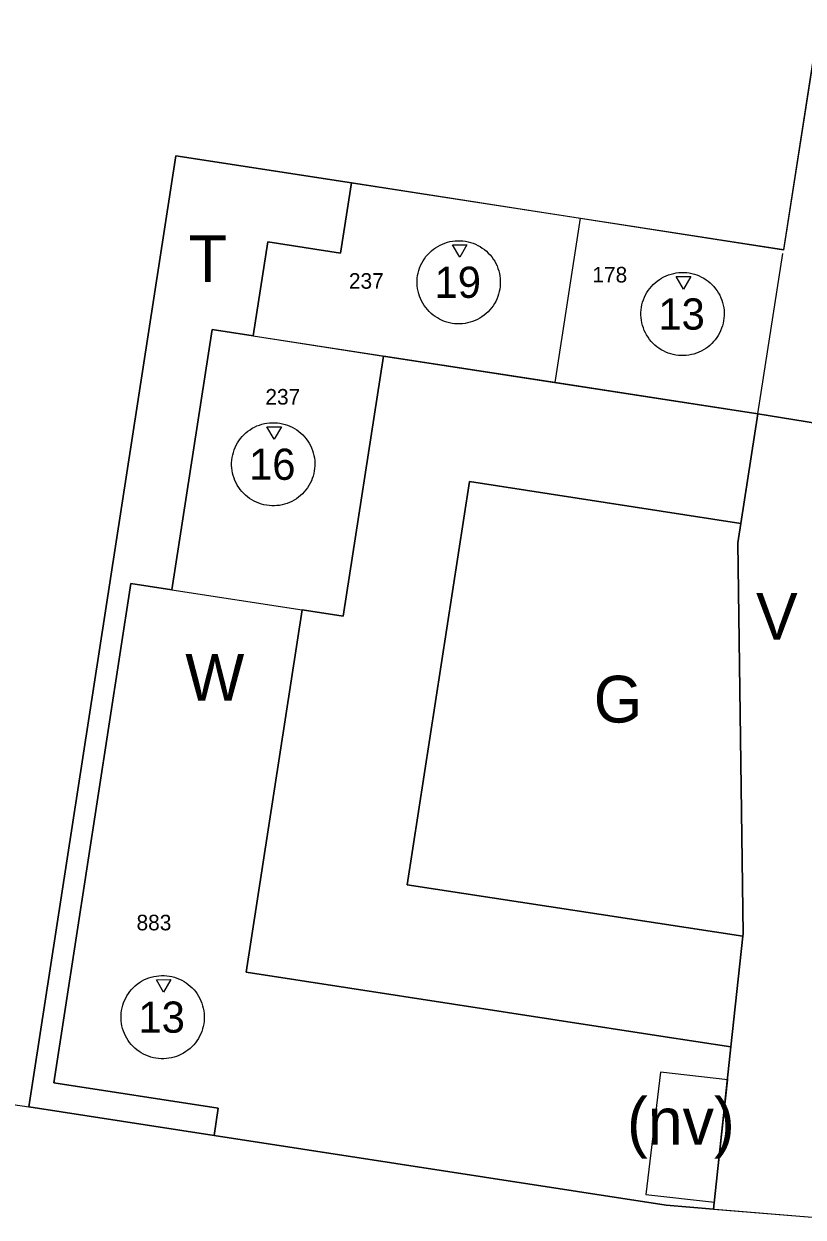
# Model space of a CAD drawing. Extents: x 104705 to 105186, y 424858 to 425816.
# Drawn here: x 104992.1 to 105048.3, y 424958.5 to 425044.5 of the extents above; entities that cross this region are included whole.
import ezdxf

# ---------------------------------------------------------------- set-up
doc = ezdxf.new("R2010")
doc.units = 0
for name, color, linetype in [('BP_ALG_bestemminggrens', 7, 'Continuous'), ('BP_BPG_Plangebied', 7, 'Continuous'), ('BP_BV_Bouwvlak', 7, 'Continuous'), ('BP_DB_Waarde - Archeologie - 3', 7, 'Continuous'), ('BP_EB_Groen', 7, 'Continuous'), ('BP_EB_Tuin', 7, 'Continuous'), ('BP_EB_Verkeer', 7, 'Continuous'), ('BP_EB_Wonen', 7, 'Continuous'), ('BP_FA_gemengd', 7, 'Continuous'), ('BP_FA_nutsvoorziening', 7, 'Continuous'), ('BP_MV_maatvoering', 7, 'Continuous'), ('BP_TXT_tekst', 7, 'Continuous'), ('Default', 7, 'Continuous')]:
    doc.layers.add(name, color=color, linetype=linetype)

msp = doc.modelspace()

# ---------------------------------------------------------------- linework, layer by layer
at = {"layer": 'BP_ALG_bestemminggrens'}
for p, q in [((105046.867, 425028.264), (105049.408, 425044.533)), ((105014.92, 425028), (105015.703, 425033.072)), ((105015.703, 425033.072), (105046.867, 425028.264)), ((105008.627, 425022.021), (105009.674, 425028.81)), ((105009.674, 425028.81), (105014.92, 425028)), ((105002.768, 425003.717), (105005.662, 425022.479)), ((105005.662, 425022.479), (105008.627, 425022.021)), ((105043.561, 425007.108), (105045.014, 425016.407)), ((105045.014, 425016.408), (105076.846, 425011.136)), ((105045.014, 425016.407), (105076.846, 425011.136)), ((105019.721, 424982.44), (105024.208, 425011.523)), ((105024.208, 425011.523), (105043.779, 425008.503)), ((105043.942, 424978.904), (105043.561, 425007.108)), ((104994.246, 424968.157), (104999.803, 425004.175)), ((104999.803, 425004.175), (105002.768, 425003.717)), ((105043.922, 424978.723), (105019.721, 424982.44)), ((105041.81, 424959.043), (105043.942, 424978.904)), ((105006.105, 424966.327), (104994.246, 424968.157)), ((105005.8, 424964.351), (105006.105, 424966.327)), ((105038.397, 424959.322), (105005.8, 424964.351)), ((105038.397, 424959.322), (105041.81, 424959.043))]:
    msp.add_line(p, q, dxfattribs=at)
msp.add_lwpolyline([(105005.8, 424964.351), (104992.458, 424966.409), (105003.045, 425035.025), (105015.703, 425033.072)], dxfattribs=at)
at = {"layer": 'BP_BPG_Plangebied'}
msp.add_line((104977.634, 424968.696), (104992.458, 424966.409), dxfattribs=at)
msp.add_lwpolyline([(104992.458, 424966.409), (105038.397, 424959.322), (105048.93, 424958.462), (105050.429, 424958.51)], dxfattribs=at)
at = {"layer": 'BP_BV_Bouwvlak'}
for p, q in [((105046.867, 425028.264), (105049.409, 425044.533)), ((105014.92, 425028), (105015.703, 425033.072)), ((105015.703, 425033.072), (105046.867, 425028.264)), ((105008.627, 425022.021), (105009.674, 425028.81)), ((105009.674, 425028.81), (105014.92, 425028)), ((105002.768, 425003.717), (105005.662, 425022.479)), ((105005.662, 425022.479), (105008.627, 425022.021)), ((105018.016, 425020.573), (105015.121, 425001.811)), ((105045.014, 425016.408), (105018.016, 425020.573)), ((105045.014, 425016.407), (105045.014, 425016.408)), ((105076.846, 425011.136), (105045.014, 425016.407)), ((104994.246, 424968.157), (104999.803, 425004.175)), ((104999.803, 425004.175), (105002.768, 425003.717)), ((105012.156, 425002.269), (105008.124, 424976.134)), ((105015.121, 425001.811), (105012.156, 425002.269)), ((105008.124, 424976.134), (105043.061, 424970.744)), ((105006.105, 424966.327), (104994.246, 424968.157)), ((105005.8, 424964.351), (105006.105, 424966.327)), ((105038.397, 424959.322), (105005.8, 424964.351))]:
    msp.add_line(p, q, dxfattribs=at)
msp.add_lwpolyline([(105043.061, 424970.744), (105041.81, 424959.043), (105038.397, 424959.322)], dxfattribs=at)
at = {"layer": 'BP_DB_Waarde - Archeologie - 3'}
msp.add_line((104977.634, 424968.696), (104992.458, 424966.409), dxfattribs=at)
msp.add_lwpolyline([(104992.458, 424966.409), (105038.397, 424959.322), (105048.93, 424958.462), (105050.429, 424958.51), (105049.681, 424981.898), (105049.681, 424981.898)], dxfattribs=at)
at = {"layer": 'BP_EB_Groen'}
for p, q in [((105024.208, 425011.523), (105019.721, 424982.44)), ((105043.779, 425008.503), (105024.208, 425011.523)), ((105043.561, 425007.108), (105043.779, 425008.503)), ((105043.942, 424978.904), (105043.561, 425007.108)), ((105019.721, 424982.44), (105043.922, 424978.723)), ((105043.922, 424978.723), (105043.942, 424978.904))]:
    msp.add_line(p, q, dxfattribs=at)
at = {"layer": 'BP_EB_Tuin'}
for p, q in [((104994.246, 424968.157), (104999.803, 425004.175)), ((104999.803, 425004.175), (105002.768, 425003.717))]:
    msp.add_line(p, q, dxfattribs=at)
for points in [[(105015.703, 425033.072), (105003.045, 425035.025), (104992.458, 424966.409), (105005.8, 424964.351)], [(105009.674, 425028.81), (105014.92, 425028), (105015.703, 425033.072)], [(105002.768, 425003.717), (105005.662, 425022.479), (105008.627, 425022.021), (105009.674, 425028.81)], [(105005.8, 424964.351), (105006.105, 424966.327), (104994.246, 424968.157)]]:
    msp.add_lwpolyline(points, dxfattribs=at)
at = {"layer": 'BP_EB_Verkeer'}
for p, q in [((105046.866, 425028.264), (105048.674, 425039.829)), ((104992.458, 424966.409), (105003.045, 425035.025)), ((105003.045, 425035.025), (105015.703, 425033.072)), ((105015.703, 425033.072), (105032.211, 425030.525)), ((105032.211, 425030.525), (105046.866, 425028.264)), ((105045.014, 425016.408), (105043.779, 425008.503)), ((105064.746, 425013.14), (105045.014, 425016.408)), ((105043.779, 425008.503), (105043.561, 425007.108)), ((105043.561, 425007.108), (105043.942, 424978.904)), ((105043.942, 424978.904), (105043.922, 424978.723)), ((104977.634, 424968.696), (104992.458, 424966.409))]:
    msp.add_line(p, q, dxfattribs=at)
for points in [[(105043.922, 424978.723), (105043.066, 424970.744), (105041.81, 424959.043)], [(105041.81, 424959.043), (105048.93, 424958.462), (105050.429, 424958.51)]]:
    msp.add_lwpolyline(points, dxfattribs=at)
at = {"layer": 'BP_EB_Wonen'}
for p, q in [((105030.381, 425018.665), (105018.016, 425020.573)), ((105045.014, 425016.408), (105030.381, 425018.665)), ((105043.779, 425008.503), (105045.014, 425016.408)), ((105008.124, 424976.134), (105038.007, 424971.524))]:
    msp.add_line(p, q, dxfattribs=at)
for points in [[(105077.145, 425011.387), (105081.418, 425038.738), (105049.408, 425044.533), (105049.287, 425043.758), (105046.856, 425028.204), (105015.703, 425033.072), (105014.92, 425028), (105009.674, 425028.81), (105008.627, 425022.021), (105005.662, 425022.479), (105002.768, 425003.717), (104999.803, 425004.175), (104994.246, 424968.157), (105006.105, 424966.327), (105005.8, 424964.351), (105038.397, 424959.322)], [(105018.016, 425020.573), (105015.121, 425001.811), (105012.156, 425002.269), (105008.124, 424976.134)], [(105038.397, 424959.322), (105041.81, 424959.043), (105043.061, 424970.744), (105038.007, 424971.524), (105008.124, 424976.134), (105012.156, 425002.269), (105015.121, 425001.811), (105018.016, 425020.573), (105045.014, 425016.407), (105077.145, 425011.387)], [(105038.007, 424971.524), (105043.061, 424970.744), (105043.922, 424978.723), (105019.721, 424982.44), (105024.208, 425011.523), (105043.779, 425008.503)]]:
    msp.add_lwpolyline(points, dxfattribs=at)
at = {"layer": 'BP_FA_gemengd'}
msp.add_lwpolyline([(105045.014, 425016.408), (105077.145, 425011.387), (105081.418, 425038.738), (105049.408, 425044.533), (105049.287, 425043.758), (105046.856, 425028.204), (105015.703, 425033.072), (105014.92, 425028), (105009.674, 425028.81), (105008.627, 425022.021), (105045.066, 425016.4)], dxfattribs=at)
at = {"layer": 'BP_FA_nutsvoorziening'}
msp.add_lwpolyline([(105036.94, 424960.104), (105041.881, 424959.534), (105042.842, 424968.375), (105037.978, 424968.913)], close=True, dxfattribs=at)
at = {"layer": 'BP_MV_maatvoering'}
for p, q in [((105030.381, 425018.665), (105032.211, 425030.525)), ((105045.014, 425016.408), (105046.798, 425027.977)), ((105008.627, 425022.021), (105018.016, 425020.573)), ((105002.768, 425003.717), (105012.156, 425002.269))]:
    msp.add_line(p, q, dxfattribs=at)
for points in [[(105026.106, 425024.517), (105026.015, 425024.352), (105025.913, 425024.193), (105025.802, 425024.042), (105025.68, 425023.898), (105025.551, 425023.761), (105025.413, 425023.632), (105025.268, 425023.512), (105025.115, 425023.403), (105024.954, 425023.302), (105024.789, 425023.212), (105024.618, 425023.133), (105024.443, 425023.065), (105024.263, 425023.008), (105024.08, 425022.962), (105023.895, 425022.927), (105023.708, 425022.905), (105023.52, 425022.894), (105023.331, 425022.894), (105023.144, 425022.908), (105022.956, 425022.932), (105022.772, 425022.968), (105022.589, 425023.016), (105022.41, 425023.076), (105022.235, 425023.146), (105022.065, 425023.227), (105021.9, 425023.319), (105021.741, 425023.421), (105021.59, 425023.532), (105021.446, 425023.653), (105021.309, 425023.782), (105021.18, 425023.92), (105021.06, 425024.066), (105020.951, 425024.219), (105020.85, 425024.379), (105020.76, 425024.544), (105020.681, 425024.715), (105020.613, 425024.891), (105020.556, 425025.071), (105020.51, 425025.254), (105020.475, 425025.438), (105020.453, 425025.626), (105020.442, 425025.813), (105020.442, 425026.002), (105020.456, 425026.19), (105020.48, 425026.377), (105020.516, 425026.562), (105020.564, 425026.745), (105020.624, 425026.923), (105020.694, 425027.099), (105020.775, 425027.268), (105020.867, 425027.433), (105020.969, 425027.592), (105021.08, 425027.744), (105021.201, 425027.888), (105021.33, 425028.024), (105021.468, 425028.153), (105021.614, 425028.273), (105021.767, 425028.383), (105021.927, 425028.483), (105022.092, 425028.573), (105022.263, 425028.653), (105022.439, 425028.72), (105022.619, 425028.777), (105022.802, 425028.824), (105022.986, 425028.858), (105023.174, 425028.881), (105023.361, 425028.891), (105023.55, 425028.891), (105023.738, 425028.878), (105023.925, 425028.854), (105024.11, 425028.818), (105024.293, 425028.77), (105024.471, 425028.71), (105024.647, 425028.639), (105024.816, 425028.558), (105024.981, 425028.467), (105025.14, 425028.365), (105025.292, 425028.254), (105025.436, 425028.132), (105025.572, 425028.003), (105025.701, 425027.865), (105025.821, 425027.72), (105025.931, 425027.567), (105026.031, 425027.406), (105026.121, 425027.241), (105026.201, 425027.07), (105026.268, 425026.895), (105026.325, 425026.715), (105026.372, 425026.532), (105026.406, 425026.347), (105026.429, 425026.16), (105026.439, 425025.972), (105026.439, 425025.783), (105026.426, 425025.596), (105026.402, 425025.408), (105026.366, 425025.224), (105026.318, 425025.041), (105026.258, 425024.862), (105026.187, 425024.687)], [(105023.51, 425027.696), (105022.988, 425028.593), (105024.027, 425028.597)], [(105042.241, 425022.229), (105042.15, 425022.064), (105042.048, 425021.905), (105041.937, 425021.754), (105041.815, 425021.61), (105041.686, 425021.473), (105041.548, 425021.344), (105041.403, 425021.224), (105041.25, 425021.115), (105041.089, 425021.014), (105040.924, 425020.924), (105040.753, 425020.845), (105040.578, 425020.777), (105040.398, 425020.72), (105040.215, 425020.674), (105040.03, 425020.639), (105039.843, 425020.617), (105039.655, 425020.606), (105039.466, 425020.606), (105039.279, 425020.62), (105039.091, 425020.644), (105038.907, 425020.68), (105038.724, 425020.728), (105038.545, 425020.788), (105038.37, 425020.858), (105038.2, 425020.939), (105038.035, 425021.031), (105037.876, 425021.133), (105037.725, 425021.244), (105037.581, 425021.365), (105037.444, 425021.494), (105037.315, 425021.632), (105037.195, 425021.778), (105037.086, 425021.931), (105036.985, 425022.091), (105036.895, 425022.256), (105036.816, 425022.427), (105036.748, 425022.603), (105036.691, 425022.783), (105036.645, 425022.966), (105036.61, 425023.15), (105036.588, 425023.338), (105036.577, 425023.525), (105036.577, 425023.714), (105036.591, 425023.902), (105036.615, 425024.089), (105036.651, 425024.274), (105036.699, 425024.457), (105036.759, 425024.635), (105036.829, 425024.811), (105036.91, 425024.98), (105037.002, 425025.145), (105037.104, 425025.304), (105037.215, 425025.456), (105037.336, 425025.6), (105037.465, 425025.736), (105037.603, 425025.865), (105037.749, 425025.985), (105037.902, 425026.095), (105038.062, 425026.195), (105038.227, 425026.285), (105038.398, 425026.365), (105038.574, 425026.432), (105038.754, 425026.489), (105038.937, 425026.536), (105039.121, 425026.57), (105039.309, 425026.593), (105039.496, 425026.603), (105039.685, 425026.603), (105039.873, 425026.59), (105040.06, 425026.566), (105040.245, 425026.53), (105040.428, 425026.482), (105040.606, 425026.422), (105040.782, 425026.351), (105040.951, 425026.27), (105041.116, 425026.179), (105041.275, 425026.077), (105041.427, 425025.966), (105041.571, 425025.844), (105041.707, 425025.715), (105041.836, 425025.577), (105041.956, 425025.432), (105042.066, 425025.279), (105042.166, 425025.118), (105042.256, 425024.953), (105042.336, 425024.782), (105042.403, 425024.607), (105042.46, 425024.427), (105042.507, 425024.244), (105042.541, 425024.059), (105042.564, 425023.872), (105042.574, 425023.684), (105042.574, 425023.495), (105042.561, 425023.308), (105042.537, 425023.12), (105042.501, 425022.936), (105042.453, 425022.753), (105042.393, 425022.574), (105042.322, 425022.399)], [(105039.645, 425025.408), (105039.123, 425026.305), (105040.162, 425026.309)], [(105012.734, 425011.393), (105012.643, 425011.228), (105012.541, 425011.069), (105012.43, 425010.918), (105012.308, 425010.774), (105012.179, 425010.637), (105012.041, 425010.508), (105011.896, 425010.388), (105011.743, 425010.279), (105011.582, 425010.178), (105011.417, 425010.088), (105011.246, 425010.009), (105011.071, 425009.941), (105010.891, 425009.884), (105010.708, 425009.838), (105010.523, 425009.803), (105010.336, 425009.781), (105010.148, 425009.77), (105009.959, 425009.77), (105009.772, 425009.784), (105009.584, 425009.808), (105009.4, 425009.844), (105009.217, 425009.892), (105009.038, 425009.952), (105008.863, 425010.022), (105008.693, 425010.103), (105008.528, 425010.195), (105008.369, 425010.297), (105008.218, 425010.408), (105008.074, 425010.529), (105007.937, 425010.658), (105007.808, 425010.796), (105007.688, 425010.942), (105007.579, 425011.095), (105007.478, 425011.255), (105007.388, 425011.42), (105007.309, 425011.591), (105007.241, 425011.767), (105007.184, 425011.947), (105007.138, 425012.13), (105007.103, 425012.314), (105007.081, 425012.502), (105007.07, 425012.689), (105007.07, 425012.878), (105007.084, 425013.066), (105007.108, 425013.253), (105007.144, 425013.438), (105007.192, 425013.621), (105007.252, 425013.799), (105007.322, 425013.975), (105007.403, 425014.144), (105007.495, 425014.309), (105007.597, 425014.468), (105007.708, 425014.62), (105007.829, 425014.764), (105007.958, 425014.9), (105008.096, 425015.029), (105008.242, 425015.149), (105008.395, 425015.259), (105008.555, 425015.359), (105008.72, 425015.449), (105008.891, 425015.529), (105009.067, 425015.596), (105009.247, 425015.653), (105009.43, 425015.7), (105009.614, 425015.734), (105009.802, 425015.757), (105009.989, 425015.767), (105010.178, 425015.767), (105010.366, 425015.754), (105010.553, 425015.73), (105010.738, 425015.694), (105010.921, 425015.646), (105011.099, 425015.586), (105011.275, 425015.515), (105011.444, 425015.434), (105011.609, 425015.343), (105011.768, 425015.241), (105011.92, 425015.13), (105012.064, 425015.008), (105012.2, 425014.879), (105012.329, 425014.741), (105012.449, 425014.596), (105012.559, 425014.443), (105012.659, 425014.282), (105012.749, 425014.117), (105012.829, 425013.946), (105012.896, 425013.771), (105012.953, 425013.591), (105013, 425013.408), (105013.034, 425013.223), (105013.057, 425013.036), (105013.067, 425012.848), (105013.067, 425012.659), (105013.054, 425012.472), (105013.03, 425012.284), (105012.994, 425012.1), (105012.946, 425011.917), (105012.886, 425011.738), (105012.815, 425011.563)], [(105010.138, 425014.572), (105009.616, 425015.469), (105010.655, 425015.473)], [(105004.762, 424971.512), (105004.67, 424971.347), (105004.568, 424971.188), (105004.457, 424971.037), (105004.336, 424970.893), (105004.207, 424970.756), (105004.069, 424970.627), (105003.923, 424970.507), (105003.77, 424970.398), (105003.61, 424970.297), (105003.445, 424970.207), (105003.274, 424970.128), (105003.098, 424970.06), (105002.918, 424970.003), (105002.735, 424969.957), (105002.551, 424969.922), (105002.363, 424969.9), (105002.176, 424969.889), (105001.987, 424969.889), (105001.799, 424969.903), (105001.612, 424969.927), (105001.427, 424969.963), (105001.244, 424970.011), (105001.066, 424970.071), (105000.89, 424970.141), (105000.721, 424970.222), (105000.556, 424970.314), (105000.397, 424970.416), (105000.245, 424970.527), (105000.101, 424970.648), (104999.965, 424970.777), (104999.836, 424970.915), (104999.716, 424971.061), (104999.606, 424971.214), (104999.506, 424971.374), (104999.416, 424971.539), (104999.336, 424971.71), (104999.269, 424971.886), (104999.212, 424972.066), (104999.165, 424972.249), (104999.131, 424972.433), (104999.108, 424972.621), (104999.098, 424972.808), (104999.098, 424972.997), (104999.111, 424973.185), (104999.135, 424973.372), (104999.171, 424973.557), (104999.219, 424973.74), (104999.279, 424973.918), (104999.35, 424974.094), (104999.431, 424974.263), (104999.522, 424974.428), (104999.624, 424974.587), (104999.735, 424974.739), (104999.857, 424974.883), (104999.986, 424975.019), (105000.124, 424975.148), (105000.269, 424975.268), (105000.422, 424975.378), (105000.583, 424975.478), (105000.748, 424975.568), (105000.919, 424975.648), (105001.094, 424975.715), (105001.274, 424975.772), (105001.457, 424975.819), (105001.642, 424975.853), (105001.829, 424975.876), (105002.017, 424975.886), (105002.206, 424975.886), (105002.393, 424975.873), (105002.581, 424975.849), (105002.765, 424975.813), (105002.948, 424975.765), (105003.127, 424975.705), (105003.302, 424975.634), (105003.472, 424975.553), (105003.637, 424975.462), (105003.796, 424975.36), (105003.947, 424975.249), (105004.091, 424975.127), (105004.228, 424974.998), (105004.357, 424974.86), (105004.477, 424974.715), (105004.586, 424974.562), (105004.687, 424974.401), (105004.777, 424974.236), (105004.856, 424974.065), (105004.924, 424973.89), (105004.981, 424973.71), (105005.027, 424973.527), (105005.062, 424973.342), (105005.084, 424973.155), (105005.095, 424972.967), (105005.095, 424972.778), (105005.081, 424972.591), (105005.057, 424972.403), (105005.021, 424972.219), (105004.973, 424972.036), (105004.913, 424971.857), (105004.843, 424971.682)], [(105002.165, 424974.691), (105001.643, 424975.588), (105002.683, 424975.592)]]:
    msp.add_lwpolyline(points, close=True, dxfattribs=at)

# ---------------------------------------------------------------- texts
for s, p in [('19', (105021.696, 425024.768)), ('13', (105037.833, 425022.48)), ('16', (105008.325, 425011.644)), ('13', (105000.353, 424971.763))]:
    msp.add_text(s, height=2.25, dxfattribs=at).set_placement(p)
at = {"layer": 'BP_TXT_tekst'}
for s, p in [('T', (105003.975, 425025.914)), ('V', (105044.869, 425000.113)), ('W', (105003.726, 424995.712)), ('G', (105033.174, 424994.137)), ('(nv)', (105035.569, 424963.692))]:
    msp.add_text(s, height=3.375, dxfattribs=at).set_placement(p)
at = {"layer": 'Default'}
for s, p in [('237', (105015.523, 425025.427)), ('178', (105033.075, 425025.879)), ('237', (105009.503, 425017.07)), ('883', (105000.214, 424979.149))]:
    msp.add_text(s, height=1.125, dxfattribs=at).set_placement(p)

doc.saveas('drawing.dxf')
